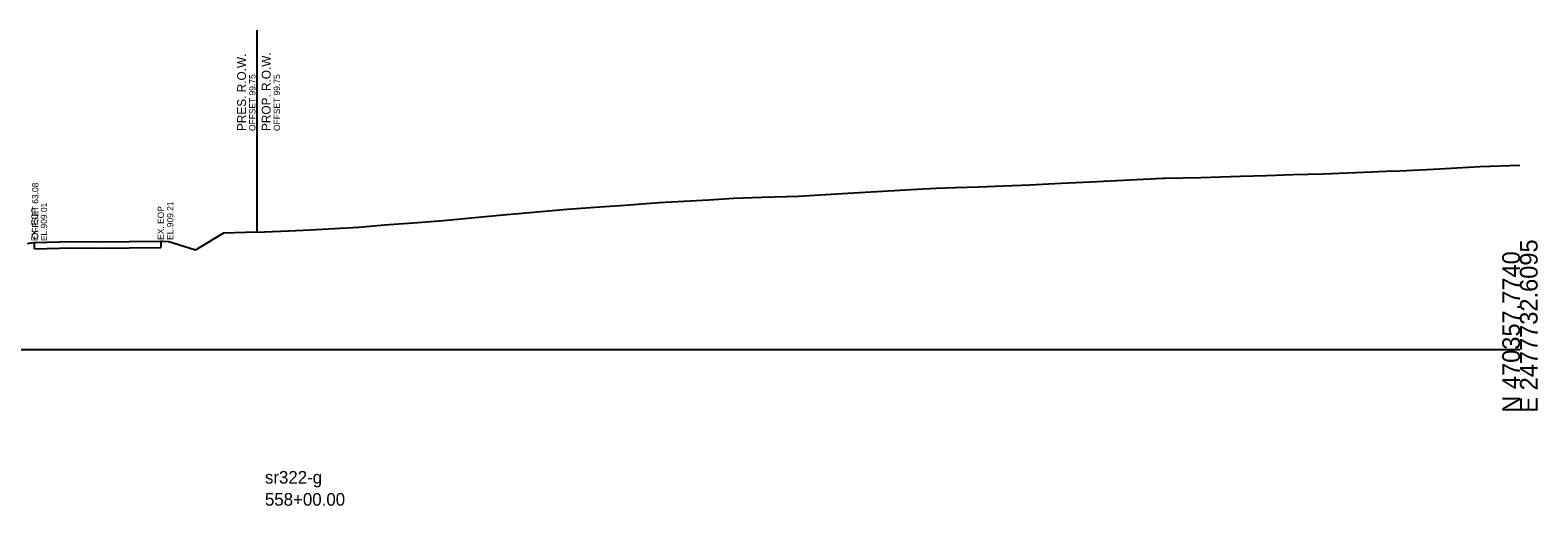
# Model space of a CAD drawing. Extents: x -26 to 4781, y -31 to 24738.
# Drawn here: x 2363.8 to 2602.8, y 8475.2 to 8550.7 of the extents above; entities that cross this region are included whole.
import ezdxf

# ---------------------------------------------------------------- set-up
doc = ezdxf.new("R2010")
doc.units = 0
for name, color, linetype in [('DESIGN - ROW - Right-of-Way and Easement Labels', 7, 'Continuous'), ('DESIGN - ROW - Right-of-Way Linework', 7, 'Continuous'), ('DESIGN - SHEET - Light Grid', 7, 'Continuous'), ('DESIGN - TYPICAL - Slope Tie Text', 7, 'Continuous'), ('DESIGN - TYPICAL - Warning Text', 7, 'Continuous'), ('SURVEY - GROUND - Existing Pavement Layer', 7, 'Continuous'), ('SURVEY - GROUND - Existing Pavement Text', 7, 'Continuous'), ('SURVEY - GROUND - Top of Ground', 7, 'Continuous'), ('SURVEY - PROPERTY - ROW Lines', 7, 'Continuous'), ('SURVEY - PROPERTY - ROW Lines Text', 7, 'Continuous')]:
    doc.layers.add(name, color=color, linetype=linetype)

msp = doc.modelspace()

# ---------------------------------------------------------------- linework, layer by layer
at = {"layer": 'DESIGN - ROW - Right-of-Way Linework'}
msp.add_line((2399.75, 8518.68), (2399.75, 8550.68), dxfattribs=at)
at = {"layer": 'DESIGN - SHEET - Light Grid'}
msp.add_line((2300, 8500), (2600, 8500), dxfattribs=at)
at = {"layer": 'SURVEY - GROUND - Existing Pavement Layer'}
for p, q in [((2364.47, 8516.01), (2364.47, 8517.01)), ((2364.47, 8516.01), (2370.38, 8516.16)), ((2370.38, 8516.16), (2374.52, 8516.11)), ((2374.52, 8516.11), (2384.48, 8516.21)), ((2384.48, 8517.21), (2384.48, 8516.21))]:
    msp.add_line(p, q, dxfattribs=at)
at = {"layer": 'SURVEY - GROUND - Top of Ground'}
msp.add_lwpolyline([(2363.38, 8516.82), (2363.94, 8516.94), (2364.47, 8517.01), (2370.38, 8517.16), (2374.52, 8517.11), (2384.48, 8517.21), (2384.82, 8517.2), (2385.74, 8517.17), (2390, 8515.81), (2390.35, 8516.02), (2394.47, 8518.55), (2397.91, 8518.65), (2400.94, 8518.7), (2404.78, 8518.84), (2408.17, 8519.02), (2415.91, 8519.45), (2419.95, 8519.79), (2424.51, 8520.12), (2429.31, 8520.51), (2438.73, 8521.37), (2441.22, 8521.58), (2448.94, 8522.28), (2454.13, 8522.64), (2458.09, 8522.93), (2463.49, 8523.32), (2467.45, 8523.54), (2471.39, 8523.75), (2475.33, 8524.02), (2479.8, 8524.21), (2485.6, 8524.35), (2492.51, 8524.79), (2505.32, 8525.49), (2507.48, 8525.6), (2510.47, 8525.73), (2514.2, 8525.83), (2518.11, 8525.98), (2522.3, 8526.15), (2527.25, 8526.4), (2531.91, 8526.63), (2543.4, 8527.2), (2543.74, 8527.21), (2549.41, 8527.3), (2555.71, 8527.53), (2559.81, 8527.63), (2564.04, 8527.78), (2568.78, 8527.91), (2576.48, 8528.21), (2578.78, 8528.3), (2580.98, 8528.37), (2586.28, 8528.63), (2593.7, 8529.04), (2600, 8529.24)], dxfattribs=at)
at = {"layer": 'SURVEY - PROPERTY - ROW Lines'}
for p, q in [((2399.75, 8540.68), (2399.75, 8550.68)), ((2399.75, 8529.68), (2399.75, 8539.68)), ((2399.75, 8518.68), (2399.75, 8528.68))]:
    msp.add_line(p, q, dxfattribs=at)

# ---------------------------------------------------------------- texts
at = {"layer": 'DESIGN - ROW - Right-of-Way and Easement Labels'}
for s, height, p in [('PROP. R.O.W.', 1.4, (2401.9, 8534.68)), ('OFFSET 99.75', 1, (2403.4, 8534.68))]:
    msp.add_text(s, height=height, rotation=90, dxfattribs=at).set_placement(p)
at = {"layer": 'DESIGN - SHEET - Light Grid'}
for s, p in [('E 2477732.6095', (2602.8, 8490)), ('N 470357.7740', (2600, 8490))]:
    msp.add_text(s, height=2.8, rotation=90, dxfattribs=at).set_placement(p)
at = {"layer": 'DESIGN - TYPICAL - Slope Tie Text'}
msp.add_text('OFFSET 63.08', height=1, rotation=90, dxfattribs=at).set_placement((2365.08, 8517.5))
at = {"layer": 'DESIGN - TYPICAL - Warning Text'}
for s, p in [('sr322-g', (2401, 8478.75)), ('558+00.00', (2401, 8475.25))]:
    msp.add_text(s, height=2, dxfattribs=at).set_placement(p)
at = {"layer": 'SURVEY - GROUND - Existing Pavement Text'}
for s, p in [('EL.909.01', (2366.47, 8517.21)), ('EX. EOP', (2384.98, 8517.41)), ('EL.909.21', (2386.48, 8517.41)), ('EX. EOP', (2364.97, 8517.21))]:
    msp.add_text(s, height=1, rotation=90, dxfattribs=at).set_placement(p)
at = {"layer": 'SURVEY - PROPERTY - ROW Lines Text'}
for s, height, p in [('PRES. R.O.W.', 1.4, (2398, 8534.68)), ('OFFSET 99.75', 1, (2399.5, 8534.68))]:
    msp.add_text(s, height=height, rotation=90, dxfattribs=at).set_placement(p)

doc.saveas('drawing.dxf')
